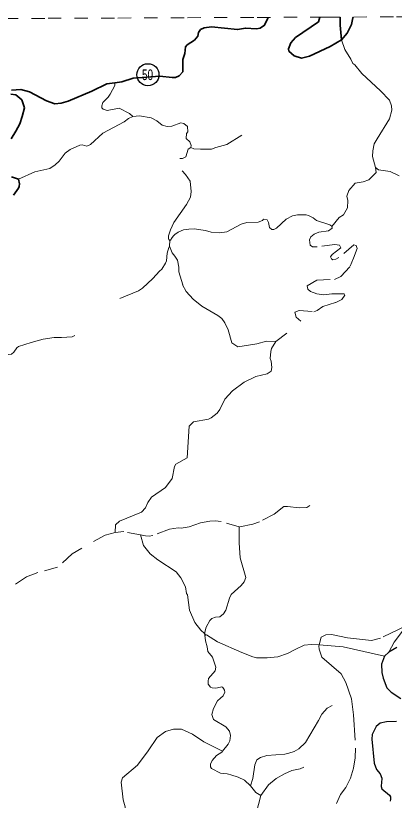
# Model space of a CAD drawing. Extents: x 423 to 448.8, y 7456.3 to 7484.
# Drawn here: x 433.23 to 436.07, y 7478.1 to 7484 of the extents above; entities that cross this region are included whole.
import ezdxf
from ezdxf.enums import TextEntityAlignment as Align

# ---------------------------------------------------------------- set-up
doc = ezdxf.new("R2010")
doc.units = 0
doc.header["$LTSCALE"] = 0.032
for name, pattern in [('LONG_DASHED', [7.5, 6, -1.5]), ('MEDIUM_DASHED', [4.5, 3, -1.5]), ('SHORT_DASHED', [2.7, 1.5, -1.2])]:
    doc.linetypes.add(name, pattern=pattern)
for name, color, linetype, lineweight in [('13', 7, 'Continuous', 25), ('15', 7, 'Continuous', 25), ('2', 7, 'Continuous', 35), ('35', 7, 'SHORT_DASHED', 13), ('5', 7, 'LONG_DASHED', 13), ('6', 7, 'MEDIUM_DASHED', 13), ('7', 7, 'Continuous', 13)]:
    doc.layers.add(name, color=color, linetype=linetype, lineweight=lineweight)
doc.layers.add('61', color=7, linetype='Continuous')

msp = doc.modelspace()

# ---------------------------------------------------------------- linework, layer by layer
at = {"layer": '13'}
msp.add_circle((434.2212, 7483.5526), 0.083, dxfattribs=at)
at = {"layer": '15'}
for points in [[(436.092, 7479.2491), (436.0323, 7479.2122), (436.0008, 7479.1824), (435.9781, 7479.124), (435.9806, 7479.0597), (435.9905, 7479.0188), (436.0179, 7478.9446), (436.0507, 7478.9116), (436.1219, 7478.8653)], [(436.0894, 7478.6929), (436.0138, 7478.6899), (435.968, 7478.6799), (435.9376, 7478.6537), (435.9062, 7478.5956), (435.9043, 7478.5597), (435.9233, 7478.3783), (435.9407, 7478.332), (435.9681, 7478.2982), (435.98, 7478.2663), (435.976, 7478.232), (435.9737, 7478.2116), (435.9737, 7478.2026), (435.9805, 7478.1857), (436.0368, 7478.1388), (436.0437, 7478.1248), (436.0448, 7478.1089), (436.0431, 7478.0943)]]:
    msp.add_lwpolyline(points, dxfattribs=at)
at = {"layer": '2'}
for points in [[(433.1957, 7483.4369), (433.266, 7483.4406), (433.3327, 7483.4249), (433.4602, 7483.3567), (433.5228, 7483.3326), (433.5684, 7483.3386), (433.6216, 7483.3532), (433.7988, 7483.4285), (433.9116, 7483.4845), (433.9729, 7483.4919), (434.026, 7483.4984), (434.1095, 7483.5265), (434.3119, 7483.5422), (434.4032, 7483.531), (434.4292, 7483.5324), (434.4555, 7483.5447), (434.4839, 7483.574), (434.483, 7483.6667), (434.4993, 7483.7114), (434.5045, 7483.7612), (434.5175, 7483.7767), (434.5721, 7483.8126), (434.5971, 7483.8429), (434.6015, 7483.8703), (434.6178, 7483.8926), (434.6454, 7483.9046), (434.7003, 7483.9115), (434.8956, 7483.892), (434.9545, 7483.9029), (435.037, 7483.8969), (435.0645, 7483.9029), (435.0979, 7483.9244), (435.122, 7483.9785), (435.1232, 7483.9835)], [(435.5128, 7483.9852), (435.5039, 7483.9512), (435.3298, 7483.8316), (435.2946, 7483.7921), (435.2775, 7483.7475), (435.2809, 7483.7303), (435.3207, 7483.6957), (435.3771, 7483.6781), (435.4363, 7483.6911), (435.5916, 7483.7639), (435.6768, 7483.8145)], [(435.6668, 7483.9858), (435.6656, 7483.9248), (435.6768, 7483.8145)], [(435.6768, 7483.8145), (435.7194, 7483.8644), (435.7518, 7483.9288), (435.7619, 7483.9802), (435.7643, 7483.9862)], [(433.193, 7483.0698), (433.23, 7483.1291), (433.2583, 7483.1841), (433.2772, 7483.239), (433.2929, 7483.3045), (433.2744, 7483.3636), (433.23, 7483.4004), (433.1911, 7483.4066)], [(433.2102, 7482.6464), (433.2489, 7482.7005), (433.2548, 7482.7117), (433.2566, 7482.7323), (433.2497, 7482.7675), (433.1973, 7482.7864)]]:
    msp.add_lwpolyline(points, dxfattribs=at)
at = {"layer": '35'}
for points in [[(426.5714, 7483.9447), (426.6604, 7483.9451), (427.1842, 7483.9476), (427.7081, 7483.9501), (428.232, 7483.9526), (428.7559, 7483.9551), (429.2797, 7483.9575), (429.8036, 7483.9599), (430.3275, 7483.9623), (430.8513, 7483.9647), (431.3752, 7483.9671), (431.8991, 7483.9695), (432.4229, 7483.9718), (432.9468, 7483.9741), (433.4707, 7483.9764), (433.9946, 7483.9787), (434.5184, 7483.981), (435.0423, 7483.9832), (435.5128, 7483.9852)], [(435.5128, 7483.9852), (435.5662, 7483.9854), (436.09, 7483.9876), (436.6139, 7483.9898), (437.1378, 7483.992), (437.6616, 7483.9942), (437.7508, 7483.9946), (437.9587, 7483.9954), (438.1502, 7483.9962)]]:
    msp.add_lwpolyline(points, dxfattribs=at)
at = {"layer": '5'}
for points in [[(436.1644, 7479.4118), (436.1624, 7479.4108), (435.9701, 7479.3194), (435.9024, 7479.3003), (435.7206, 7479.321), (435.6021, 7479.345), (435.5591, 7479.3442), (435.5231, 7479.3253), (435.508, 7479.2673), (435.5064, 7479.2611), (435.5092, 7479.2351), (435.5286, 7479.1744), (435.6742, 7479.0513), (435.7103, 7478.9861), (435.7511, 7478.8627), (435.766, 7478.7426), (435.782, 7478.4926), (435.7801, 7478.418), (435.7662, 7478.3415), (435.744, 7478.266), (435.7079, 7478.196), (435.6699, 7478.1428), (435.6394, 7478.077)], [(436.0323, 7479.2122), (436.0728, 7479.2872), (436.1644, 7479.4118)]]:
    msp.add_lwpolyline(points, dxfattribs=at)
at = {"layer": '6'}
for points in [[(435.3716, 7481.7003), (435.3359, 7481.7299), (435.3265, 7481.7687), (435.3576, 7481.7812), (435.468, 7481.7718), (435.4929, 7481.7812), (435.5364, 7481.8107), (435.6336, 7481.8415), (435.6802, 7481.8633), (435.7004, 7481.896), (435.6973, 7481.9054), (435.6678, 7481.9069), (435.604, 7481.9069), (435.5434, 7481.8992), (435.4921, 7481.9054), (435.4424, 7481.9224), (435.4226, 7481.9413), (435.4183, 7481.9671), (435.4905, 7482.0088), (435.6238, 7482.0147), (435.6711, 7482.0362), (435.7421, 7482.1131), (435.7665, 7482.173), (435.7943, 7482.2458), (435.7874, 7482.2688), (435.7694, 7482.2747), (435.656, 7482.179), (435.6341, 7482.166), (435.6122, 7482.162), (435.6012, 7482.169), (435.5943, 7482.184), (435.6072, 7482.2009), (435.6705, 7482.2513), (435.6605, 7482.2722), (435.6277, 7482.2771), (435.4944, 7482.2592), (435.4575, 7482.2602), (435.4416, 7482.2721), (435.4356, 7482.311), (435.4461, 7482.3334), (435.47, 7482.3553), (435.5069, 7482.3702), (435.5795, 7482.3802), (435.6069, 7482.3995), (435.6046, 7482.4128), (435.6588, 7482.479), (435.6905, 7482.5004), (435.7206, 7482.5511), (435.724, 7482.6069), (435.7162, 7482.6402), (435.7321, 7482.6822), (435.78, 7482.7382), (435.8389, 7482.7472), (435.8808, 7482.7633), (435.9147, 7482.7952), (435.9366, 7482.8173), (435.9317, 7482.8543), (435.9544, 7482.8375), (436.0422, 7482.8245), (436.1102, 7482.7932)], [(435.2427, 7480.3068), (435.1708, 7480.25), (435.0593, 7480.1935), (435.0103, 7480.1747), (434.9074, 7480.1545), (434.7725, 7480.1944), (434.7269, 7480.2005), (434.6866, 7480.1987), (434.6179, 7480.185), (434.5311, 7480.154), (434.4719, 7480.1446), (434.4486, 7480.1472), (434.3843, 7480.1386), (434.2588, 7480.0905), (434.2314, 7480.0853), (434.2022, 7480.0867), (434.1666, 7480.0938), (434.0416, 7480.1188), (433.9744, 7480.1128), (433.9, 7480.0931), (433.6522, 7479.9531), (433.5412, 7479.8517), (433.3932, 7479.8115), (433.3095, 7479.7793), (433.2275, 7479.723)]]:
    msp.add_lwpolyline(points, dxfattribs=at)
at = {"layer": '7'}
for p, q in [((434.3863, 7482.3061), (434.3841, 7482.2633)), ((435.2651, 7481.6113), (435.1839, 7481.5489))]:
    msp.add_line(p, q, dxfattribs=at)
for points in [[(435.6768, 7483.8145), (435.7017, 7483.7414), (435.7473, 7483.6693), (435.7627, 7483.6366), (435.7764, 7483.6281), (435.8288, 7483.5628), (435.9705, 7483.4305), (436.0367, 7483.3618), (436.0521, 7483.3198), (436.055, 7483.2859), (436.0362, 7483.2203), (435.9452, 7483.0705), (435.9233, 7483.0335), (435.9131, 7482.9808), (435.9086, 7482.9378), (435.9317, 7482.8543)], [(433.9729, 7483.4919), (433.9718, 7483.4711), (433.9377, 7483.4074), (433.9225, 7483.3841), (433.8817, 7483.3426), (433.8749, 7483.3198), (433.8758, 7483.3034), (433.8852, 7483.294), (433.9153, 7483.2828), (434.0055, 7483.3019), (434.0841, 7483.26), (434.1085, 7483.2396)], [(433.2497, 7482.7675), (433.3722, 7482.8228), (433.485, 7482.8491), (433.5254, 7482.8757), (433.5537, 7482.9024), (433.5992, 7482.9633), (433.6371, 7482.9899), (433.7092, 7483.0235), (433.7264, 7483.026), (433.7633, 7483.0157), (433.79, 7483.0286), (433.8827, 7483.1145), (434.0419, 7483.1987), (434.0757, 7483.2236), (434.1085, 7483.2396)], [(434.1085, 7483.2396), (434.1573, 7483.2445), (434.2464, 7483.2281), (434.2897, 7483.2059), (434.3284, 7483.1746), (434.3654, 7483.1634), (434.4014, 7483.1651), (434.4702, 7483.1901), (434.4925, 7483.1858), (434.5191, 7483.1643), (434.5217, 7483.124), (434.5122, 7483.1102), (434.5097, 7483.0731), (434.5356, 7483.0471), (434.5475, 7483.0212), (434.544, 7483.0068)], [(434.544, 7483.0068), (434.5679, 7482.9968), (434.6167, 7482.9928), (434.6993, 7482.9928), (434.7321, 7483.0048), (434.8152, 7483.0283), (434.9262, 7483.0986)], [(434.544, 7483.0068), (434.5242, 7482.9925), (434.5062, 7482.9359), (434.4822, 7482.923), (434.4624, 7482.923)], [(434.4793, 7482.8294), (434.5042, 7482.8035), (434.5388, 7482.7537), (434.5464, 7482.676), (434.5411, 7482.6316), (434.5105, 7482.5777), (434.4169, 7482.442), (434.3911, 7482.3879), (434.3773, 7482.3419), (434.376, 7482.3368), (434.3759, 7482.3308), (434.3759, 7482.3246), (434.3768, 7482.3192), (434.3789, 7482.3143), (434.3863, 7482.3061)], [(434.3863, 7482.3061), (434.3911, 7482.3098), (434.4037, 7482.3296), (434.4127, 7482.3408), (434.4244, 7482.3523), (434.4497, 7482.3697), (434.4895, 7482.386), (434.5293, 7482.3932), (434.5692, 7482.3936), (434.6543, 7482.3822), (434.6977, 7482.3682), (434.7604, 7482.3647), (434.8154, 7482.3716), (434.9219, 7482.4283), (434.9649, 7482.4429), (435.0507, 7482.4446), (435.0825, 7482.4583), (435.0911, 7482.4669), (435.1177, 7482.4618), (435.1271, 7482.442), (435.1358, 7482.4043), (435.1538, 7482.3896), (435.1675, 7482.3888), (435.1873, 7482.3991), (435.2603, 7482.4661), (435.3075, 7482.491), (435.3462, 7482.5004), (435.4114, 7482.4996), (435.4286, 7482.4944), (435.4638, 7482.4772), (435.4878, 7482.4575), (435.5884, 7482.424), (435.6046, 7482.4148), (435.6046, 7482.4128)], [(434.3841, 7482.2633), (434.3778, 7482.2554), (434.3672, 7482.212), (434.3601, 7482.1552), (434.353, 7482.1364), (434.3271, 7482.0912), (434.3087, 7482.0771), (434.2574, 7482.02), (434.1799, 7481.9482), (434.1515, 7481.9293), (434.0098, 7481.8709)], [(435.1839, 7481.5489), (435.1123, 7481.5499), (435.0401, 7481.5304), (434.8968, 7481.5085), (434.8515, 7481.5376), (434.8257, 7481.6347), (434.8008, 7481.6871), (434.7759, 7481.7206), (434.7467, 7481.7429), (434.6273, 7481.8142), (434.5629, 7481.8666), (434.5079, 7481.9233), (434.4804, 7481.9731), (434.4832, 7481.9747), (434.4527, 7482.0709), (434.4536, 7482.1067), (434.4445, 7482.1591), (434.4246, 7482.1882), (434.405, 7482.2132), (434.3841, 7482.2633)], [(433.1198, 7481.4483), (433.131, 7481.4461), (433.1968, 7481.453), (433.213, 7481.4688), (433.2364, 7481.5007), (433.249, 7481.5112), (433.3442, 7481.54), (433.4349, 7481.5641), (433.5172, 7481.5788), (433.5729, 7481.577), (433.6529, 7481.5818), (433.671, 7481.594)], [(433.9744, 7480.1128), (433.9778, 7480.1708), (434.0085, 7480.1965), (434.1739, 7480.2665), (434.2028, 7480.2972), (434.2207, 7480.3374), (434.2497, 7480.3784), (434.3536, 7480.4501), (434.4039, 7480.5193), (434.4203, 7480.6076), (434.4315, 7480.6255), (434.5176, 7480.674), (434.5321, 7480.9115), (434.5457, 7480.927), (434.5646, 7480.945), (434.6771, 7480.9648), (434.6977, 7480.9751), (434.7433, 7481.0095), (434.7613, 7481.0361), (434.7991, 7481.1134), (434.8575, 7481.1769), (434.9459, 7481.2431), (435.0336, 7481.2843), (435.1185, 7481.304), (435.1469, 7481.3247), (435.1529, 7481.3513), (435.1478, 7481.4011), (435.1409, 7481.4191), (435.1443, 7481.4733), (435.1503, 7481.4956), (435.1839, 7481.5489)], [(435.2427, 7480.3068), (435.2698, 7480.3087), (435.3593, 7480.2966), (435.4166, 7480.2998), (435.4396, 7480.3154)], [(434.9074, 7480.1545), (434.9073, 7480.0338), (434.9137, 7479.9215), (434.9565, 7479.7743), (434.9442, 7479.7427), (434.9236, 7479.7143), (434.8471, 7479.6465), (434.8343, 7479.6199), (434.8076, 7479.5279), (434.7905, 7479.5005), (434.7613, 7479.4799), (434.7295, 7479.4756), (434.702, 7479.4653), (434.6874, 7479.4507), (434.6582, 7479.4), (434.6471, 7479.3536)], [(434.6471, 7479.3536), (434.6194, 7479.3781), (434.5741, 7479.437), (434.5334, 7479.5276), (434.5182, 7479.643), (434.5122, 7479.6533), (434.5028, 7479.7041), (434.4701, 7479.7728), (434.4332, 7479.8165), (434.2958, 7479.9076), (434.2391, 7479.9522), (434.1878, 7480.0148), (434.1666, 7480.0938)], [(434.6471, 7479.3536), (434.6565, 7479.3416), (434.6616, 7479.3424), (434.7458, 7479.2918), (434.9271, 7479.211), (435.0112, 7479.1776), (435.037, 7479.1716), (435.1168, 7479.1699), (435.1976, 7479.1784), (435.2714, 7479.2033), (435.3342, 7479.2368), (435.3951, 7479.266), (435.4475, 7479.272), (435.508, 7479.2673), (435.6897, 7479.2531), (436.0008, 7479.1824)], [(434.7819, 7478.4688), (434.8249, 7478.5215), (434.8363, 7478.5475), (434.8413, 7478.5874), (434.8354, 7478.6203), (434.807, 7478.6533), (434.7155, 7478.7061), (434.7011, 7478.745), (434.715, 7478.7889), (434.7444, 7478.8468), (434.7673, 7478.8667), (434.786, 7478.8853), (434.7987, 7478.9136), (434.7971, 7478.927), (434.7907, 7478.9405), (434.7845, 7478.9482), (434.7764, 7478.9521), (434.7668, 7478.9495), (434.7325, 7478.9436), (434.7053, 7478.9458), (434.6918, 7478.9503), (434.6748, 7478.9723), (434.6747, 7478.9855), (434.6742, 7478.9952), (434.6766, 7479.016), (434.7259, 7479.0722), (434.7329, 7479.1002), (434.7065, 7479.176), (434.6726, 7479.2189), (434.6671, 7479.2539), (434.6532, 7479.2973), (434.6498, 7479.342), (434.6471, 7479.3536)], [(434.9918, 7478.2087), (435.0112, 7478.2637), (435.0241, 7478.366), (435.0412, 7478.4046), (435.0687, 7478.4226), (435.116, 7478.4355), (435.2508, 7478.4467), (435.2809, 7478.4544), (435.3212, 7478.4673), (435.3565, 7478.4879), (435.4054, 7478.5343), (435.5037, 7478.699), (435.5275, 7478.7466), (435.5684, 7478.7925), (435.6075, 7478.8113)], [(433.7943, 7477.6764), (433.8295, 7477.7667), (433.8699, 7477.8288), (433.9018, 7477.8608), (434.0261, 7477.9633), (434.0446, 7478.0002), (434.0497, 7478.0506), (434.0364, 7478.1032), (434.0194, 7478.2355), (434.0312, 7478.2691), (434.1438, 7478.3649), (434.2244, 7478.4724), (434.2916, 7478.5716), (434.3538, 7478.6169), (434.4126, 7478.6354), (434.4748, 7478.6354), (434.5571, 7478.5968), (434.6412, 7478.5396), (434.7819, 7478.4688)], [(434.9918, 7478.2087), (434.9484, 7478.2513), (434.8991, 7478.2735), (434.8453, 7478.2921), (434.8265, 7478.2955), (434.8162, 7478.2989), (434.7682, 7478.3041), (434.7005, 7478.3382), (434.6916, 7478.3525), (434.6915, 7478.3704), (434.7035, 7478.3997), (434.7358, 7478.4367), (434.7765, 7478.4622), (434.7819, 7478.4688)], [(435.0702, 7478.1365), (435.1281, 7478.2165), (435.185, 7478.264), (435.2488, 7478.2988), (435.3033, 7478.3243), (435.3647, 7478.3359), (435.3937, 7478.3499)], [(435.0702, 7478.1365), (435.0324, 7478.1578), (434.9918, 7478.2087)], [(434.9936, 7477.8366), (435.0212, 7477.9439), (435.0702, 7478.1365)]]:
    msp.add_lwpolyline(points, dxfattribs=at)

# ---------------------------------------------------------------- texts
at = {"layer": '61', "width": 0.7}
msp.add_text('50', height=0.08, dxfattribs=at).set_placement((434.2188, 7483.5124), align=Align.CENTER)

doc.saveas('drawing.dxf')
